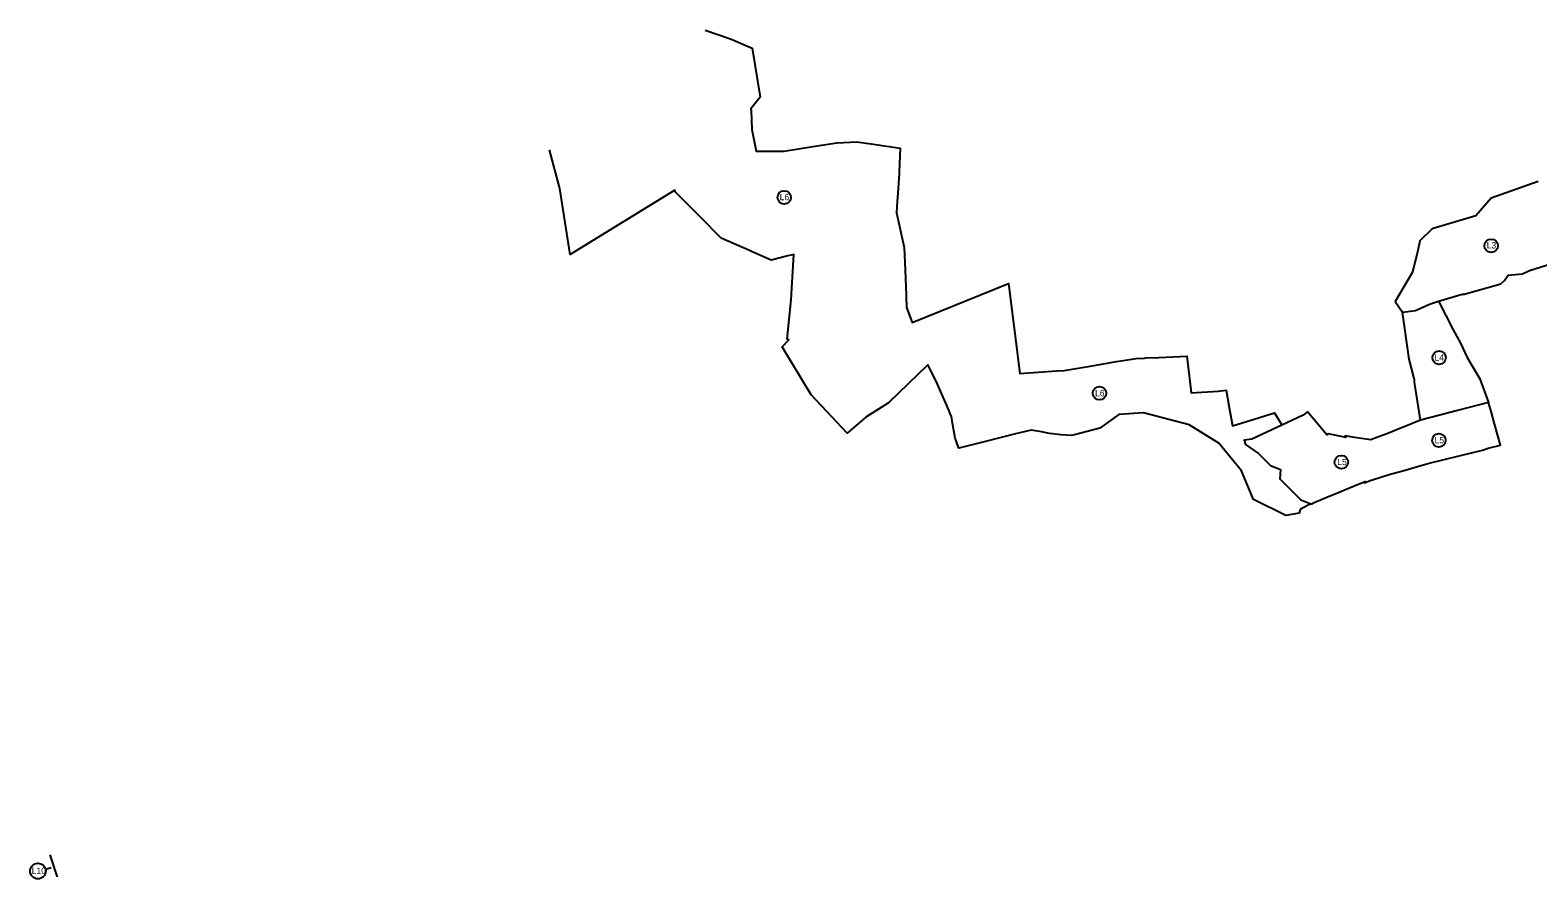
# Model space of a CAD drawing. Extents: x -445081 to -434932, y -1146827 to -1130103.
# Drawn here: x -445081 to -442214, y -1133705 to -1132092 of the extents above; entities that cross this region are included whole.
import ezdxf

# ---------------------------------------------------------------- set-up
doc = ezdxf.new("R2010")
doc.units = 0
for name, color, linetype in [('Vrstva 32', 7, 'Continuous'), ('Vrstva 33', 7, 'Continuous'), ('Vrstva 36', 7, 'Continuous')]:
    doc.layers.add(name, color=color, linetype=linetype)

msp = doc.modelspace()

# ---------------------------------------------------------------- linework, layer by layer
at = {"layer": 'Vrstva 32'}
for points in [[(-442213.7, -1132379.6), (-442303.1, -1132411), (-442332, -1132445), (-442413.2, -1132469.2), (-442415.9, -1132470.2), (-442438.4, -1132492.1), (-442442.6, -1132510.8), (-442452.5, -1132552.2), (-442485.4, -1132607.7), (-442471.6, -1132628.2), (-442447, -1132625.1), (-442420.2, -1132612.5), (-442403.1, -1132607.3), (-442358.4, -1132593.7), (-442358.4, -1132593.7), (-442354.7, -1132593.7), (-442284.9, -1132574), (-442277.9, -1132567.9), (-442270.6, -1132557.9), (-442243.2, -1132554.9), (-442230.4, -1132548.5), (-442129.2, -1132516.8)], [(-442213.7, -1132379.6), (-442303.1, -1132411), (-442332, -1132445), (-442413.2, -1132469.2), (-442415.9, -1132470.2), (-442438.4, -1132492.1), (-442442.6, -1132510.8), (-442452.5, -1132552.2), (-442485.4, -1132607.7)], [(-442485.4, -1132607.7), (-442471.6, -1132628.2), (-442447, -1132625.1), (-442420.2, -1132612.5), (-442403.1, -1132607.3), (-442358.4, -1132593.7), (-442354.7, -1132593.7), (-442284.9, -1132574), (-442277.9, -1132567.9), (-442270.6, -1132557.9), (-442243.2, -1132554.9), (-442230.4, -1132548.5), (-442129.2, -1132516.8)], [(-442309, -1132886.8), (-442285.2, -1132881.1), (-442296.6, -1132840.1), (-442302.5, -1132818.9), (-442307.9, -1132799.8), (-442369.7, -1132815.7), (-442403.5, -1132824.5), (-442437.2, -1132833.3), (-442454.6, -1132840.1), (-442484, -1132852.3), (-442499.3, -1132858.8), (-442522.6, -1132867.2), (-442532.1, -1132870.8), (-442562.6, -1132866.1), (-442580.6, -1132863.3), (-442579.6, -1132866.6), (-442612, -1132859.2), (-442615.2, -1132861.2), (-442652.5, -1132817.5), (-442660.2, -1132823.9), (-442701.1, -1132843), (-442758.2, -1132869.6), (-442772.4, -1132871.4), (-442770.3, -1132879.6), (-442745.5, -1132896.6), (-442722.7, -1132919.5), (-442703.6, -1132927.2), (-442704.9, -1132945.1), (-442665, -1132984.7), (-442645.8, -1132992.7), (-442643.5, -1132991.5), (-442639.5, -1132989.6), (-442611.1, -1132978), (-442596.7, -1132972.3), (-442583.4, -1132966.7), (-442554.2, -1132954.6), (-442542.3, -1132949.9), (-442544.6, -1132952.4), (-442540.7, -1132951), (-442532.9, -1132947.8), (-442527, -1132946), (-442497.2, -1132936.8), (-442466.4, -1132928.3), (-442447.5, -1132922.7), (-442420.8, -1132914.9), (-442364.2, -1132900.9), (-442319.8, -1132890.2), (-442309, -1132886.8)], [(-442285.2, -1132881.1), (-442296.6, -1132840.1), (-442302.5, -1132818.9), (-442307.9, -1132799.8), (-442307.9, -1132799.8), (-442369.7, -1132815.7), (-442403.5, -1132824.5), (-442403.5, -1132824.5), (-442437.2, -1132833.3), (-442454.6, -1132840.1), (-442484, -1132852.3), (-442499.3, -1132858.8), (-442522.6, -1132867.2), (-442532.1, -1132870.8), (-442562.6, -1132866.1), (-442580.6, -1132863.3), (-442579.6, -1132866.6), (-442612, -1132859.2), (-442615.2, -1132861.2), (-442652.5, -1132817.5), (-442660.2, -1132823.9), (-442660.2, -1132823.9), (-442701.1, -1132843), (-442758.2, -1132869.6), (-442758.2, -1132869.6), (-442772.4, -1132871.4), (-442770.3, -1132879.6), (-442745.5, -1132896.6), (-442722.7, -1132919.5), (-442703.6, -1132927.2), (-442704.9, -1132945.1), (-442665, -1132984.7), (-442645.8, -1132992.7), (-442642.5, -1132992.5)]]:
    msp.add_lwpolyline(points, dxfattribs=at)
at = {"layer": 'Vrstva 33'}
for points in [[(-443797.6, -1132091.8), (-443748.9, -1132108.2), (-443748.9, -1132108.2), (-443707.9, -1132126.3), (-443692.6, -1132219.1), (-443692.6, -1132219.1), (-443710.2, -1132241.2), (-443710.1, -1132244.3), (-443708.7, -1132281), (-443700.4, -1132321.8), (-443646.8, -1132321.8), (-443596.6, -1132313.9), (-443576.1, -1132310.6), (-443547.1, -1132306), (-443509, -1132304), (-443486.5, -1132307.1), (-443481.6, -1132307.8), (-443426.4, -1132315.9), (-443428.4, -1132360.5), (-443428.3, -1132364.5), (-443431.7, -1132410.4), (-443432.1, -1132416.4), (-443433.4, -1132439.1), (-443418.8, -1132505.1), (-443417.1, -1132548.1), (-443415.2, -1132596), (-443415, -1132599.7), (-443414.3, -1132618.9), (-443403.8, -1132647.4), (-443220.4, -1132573.8), (-443199, -1132744.6), (-443199, -1132744.6), (-443164.2, -1132742.2), (-443129.3, -1132739.8), (-443114.3, -1132738.9), (-443111.3, -1132738.6), (-443099.5, -1132736.5), (-443061.5, -1132729.8), (-443061.5, -1132729.8), (-443061.5, -1132729.8), (-443015.2, -1132721.8), (-442977.8, -1132715.9), (-442962.3, -1132715.2), (-442959.8, -1132714.9), (-442935.1, -1132714), (-442907.7, -1132712.9), (-442894.7, -1132712.4), (-442881.8, -1132711.8), (-442874.1, -1132775.7), (-442873.5, -1132781.6), (-442822.1, -1132778.2), (-442806.9, -1132776.4), (-442800.9, -1132809.5), (-442794.6, -1132844), (-442743.2, -1132828), (-442714.7, -1132819.2), (-442714.7, -1132819.2), (-442702.4, -1132840.6), (-442701.1, -1132843)], [(-442645.8, -1132992.7), (-442648.5, -1132994), (-442665.8, -1133002.6), (-442666.7, -1133006), (-442667.8, -1133010.1), (-442693.6, -1133014.9), (-442755.1, -1132984.5), (-442778, -1132929.5), (-442820.7, -1132876.9), (-442877.4, -1132842.4), (-442963.8, -1132819.4), (-443011, -1132822.8), (-443046.8, -1132848.6), (-443095, -1132861.1), (-443101, -1132862.6), (-443120.6, -1132861.5), (-443143, -1132858.5), (-443157.7, -1132855.7), (-443177.3, -1132852.1), (-443207.3, -1132859.6), (-443264.6, -1132874), (-443314.9, -1132886.6), (-443316.1, -1132883.4), (-443321.9, -1132867.7), (-443327, -1132839), (-443329.2, -1132826.1), (-443332.2, -1132819.2), (-443333.7, -1132815.9), (-443333.7, -1132815.9), (-443333.7, -1132815.9), (-443333.7, -1132815.9), (-443358.3, -1132759.2), (-443374.2, -1132728.1), (-443374.2, -1132728.1), (-443448.7, -1132800.5), (-443491.7, -1132827.4), (-443527.2, -1132857.8), (-443596, -1132785.4), (-443651, -1132694), (-443638, -1132680.3), (-443638, -1132680.3), (-443641.5, -1132679.3), (-443633.9, -1132604.4), (-443633.9, -1132604.4), (-443632.6, -1132582.2), (-443632.6, -1132582.2), (-443629, -1132518.3), (-443629, -1132518.3), (-443639.9, -1132520.7), (-443671.8, -1132528.9), (-443709.2, -1132512.6), (-443713.3, -1132510.7), (-443713.3, -1132510.7), (-443713.3, -1132510.7), (-443766.7, -1132487.4), (-443806.2, -1132447.4), (-443853.9, -1132399.9), (-443855, -1132395.9), (-443855, -1132395.9), (-443951.8, -1132455.4), (-443951.8, -1132455.4), (-444054, -1132518.1), (-444054, -1132518.1), (-444073.5, -1132392.7), (-444093.2, -1132319.4)], [(-442403.1, -1132607.3), (-442375.2, -1132661.9), (-442361.4, -1132687.1), (-442348.8, -1132714.2), (-442324.9, -1132754.9), (-442307.9, -1132799.8)], [(-442437.2, -1132833.3), (-442448.5, -1132761.2), (-442449.1, -1132756.8), (-442449.9, -1132751.7), (-442459, -1132717.2), (-442471.6, -1132628.2)], [(-445043.3, -1133659.7), (-445029.8, -1133700.5), (-445030, -1133701.9)]]:
    msp.add_lwpolyline(points, dxfattribs=at)
at = {"layer": 'Vrstva 36'}
msp.add_line((-445051.5, -1133686.8), (-445040.8, -1133683.9), dxfattribs=at)
for centre, radius in [((-443647, -1132409.8), 12.8), ((-442303.1, -1132501.7), 12.8), ((-442402, -1132714.5), 12.8), ((-443047.7, -1132782.1), 12.8), ((-442402.4, -1132871.8), 12.8), ((-442587.8, -1132913.1), 12.8), ((-445065.8, -1133690.7), 14.8)]:
    msp.add_circle(centre, radius, dxfattribs=at)

# ---------------------------------------------------------------- texts
for s, p in [('L6', (-443655.5, -1132415.1)), ('L3', (-442311.4, -1132506.9)), ('L4', (-442410.6, -1132720.2)), ('L6', (-443056, -1132788.1)), ('L5', (-442410.6, -1132877.5)), ('L5', (-442595.5, -1132918.9)), ('L10', (-445077.5, -1133696))]:
    msp.add_text(s, height=12, dxfattribs=at).set_placement(p)

doc.saveas('drawing.dxf')
